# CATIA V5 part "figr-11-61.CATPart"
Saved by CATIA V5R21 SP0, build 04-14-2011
Part number: Part1
Bounding box of the stored display mesh (mm): x -54 to 54, y -91.936 to 93.838, z -12.649 to 110.643
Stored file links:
  D:\CATIA V5R21 E-RESOURCES\CATIA-V5R21\catia-v5r21-prt\c11-catia-v5r21-prt\c11-catia-v5r21-figr-11-61.CATPart
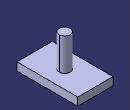
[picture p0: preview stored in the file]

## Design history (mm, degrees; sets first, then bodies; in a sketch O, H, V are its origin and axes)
Set1
  Loft1: Sections (Sketch4; Sketch3)
Body1 (main body)
  Sketch1 on yz-plane, origin (0, 0, 0), H (0, 1, 0), V (0, 0, 1)
    point P1 (93.8379, 11.643)
    line L1 (93.8379, 11.643) -> (93.8379, -12.6487)
    line L2 (93.8379, -12.6487) -> (-91.9362, -12.6487)
    line L3 (-91.9362, -12.6487) -> (-91.9362, 11.643)
    line L4 (-91.9362, 11.643) -> (93.8379, 11.643)
    point P5 (93.8379, 11.643)
    vertical: L1 V, L3 V
    horizontal: L2 H, L4 H
    coincidence: P5 P1
  Pad1: profile Sketch1, direction (1, 0, 0), length 54, mirrored extent
  Sketch2 on face of Pad1, origin (0, 0, 11.643), H (1, 0, 0), V (0, 1, 0)
    circle A1 centre (0, 0) radius 16.7533
    point P1 (16.7533, 0)
    coincidence: A1 P1, P1 H
  Pad2: profile Sketch2, direction (0, 0, 1), length 99
  Sketch3 on face of Pad2, origin (0, 0, 110.643), H (1, 0, 0), V (0, 1, 0)
    point P1 (0, 42.8937)
    point P2 (33.9651, 0)
    projected circle E1 centre (0, 0) radius 16.7533 from edge [face of Pad2 | face of Pad2]
    circle A1 centre (0, 0) radius 33.9651
    point P3 (0, 33.9651)
    coincidence: P1 V, P2 H, A1 P2, A1 P3, P3 V
  Sketch4 on face of Pad1, origin (0, 0, 11.643), H (1, 0, 0), V (0, 1, 0)
    ellipse A1 centre (0, 0) semi-axes 69.9141, 43.1918 rotation 90
    point P1 (0, 69.9141)
    point P2 (43.1918, 0)
    coincidence: P1 V, P2 H, A1 P1, A1 P2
